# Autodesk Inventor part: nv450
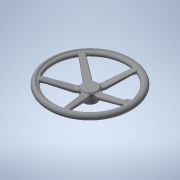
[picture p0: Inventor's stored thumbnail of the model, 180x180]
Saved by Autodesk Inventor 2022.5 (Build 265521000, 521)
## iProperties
Created: 2016-12
Part Number: nv450
Material: 一般
Document SubType Name: Modeling
Designer: imaocorp
Density: 1 g/cm^3
Appearance: 既定
Author: imaocorp
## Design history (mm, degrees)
node "nv450.x_t1"
node "nv450"
node "Base1"
